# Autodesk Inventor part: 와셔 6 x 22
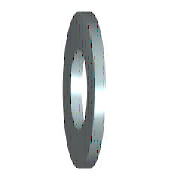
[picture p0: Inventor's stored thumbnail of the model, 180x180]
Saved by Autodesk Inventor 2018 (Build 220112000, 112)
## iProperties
Created: 2012-02
Part Number: 와셔 6 x 22
Material: 강철
Description: 평면 와셔 - 초대형 시리즈 - 제품 등급 C
Document SubType Name: Modeling
Standard: ISO 7094
Designer: mdu-01
Standard Revision: Second edition 2000-06-01
Standards Organization: ISO
Language: ko-KR
Size Designation: ST 6 - 100 HV
Categories: <MemberInstance><Categories><Category DisplayName="조임쇠" InternalName="e4da775c-781d-43d5-af7c-5136215cf5a6" Mnemonic="FSTN"><Category DisplayName="와셔" InternalN
Density: 7.85 g/cm^3
Appearance: 파란색 - 벽 페인트 - 광택
IsCustomPart: 1
Author: mdu-01
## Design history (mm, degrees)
sketch "스케치"
  geometry: C1 r 11 at (0, 0); C2 r 3.3 at (0, 0); 1 further point
  constraints: 2 centre point, 2 coincident
  dimensions: "d0" = 6.6 diameter of C2 (= SD1); "d1" = 22 diameter of C1 (= SD2)
extrude "본체" new body sketch "스케치" distance "d2" = 2 (= SD); taper "d3" = 0 deg
workaxis "Work Axis1"
workplane "Work Plane1"
body "Solid1"
other parameters: "SD1" = 6.6 [user parameter; used in 1 equation term], "SD2" = 22 [user parameter; used in 1 equation term], "SD" = 2 [user parameter; used in 1 equation term], "d4" = 0, "d5" = 0, "d6" = 0, "d7" = 0, "NND" = 6 [user parameter]
